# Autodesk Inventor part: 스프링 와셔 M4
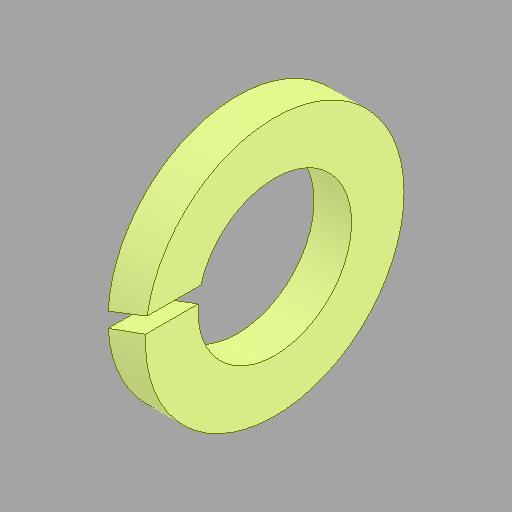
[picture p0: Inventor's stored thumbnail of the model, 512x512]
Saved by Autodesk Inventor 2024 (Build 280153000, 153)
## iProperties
Created: 2024-05
Part Number: 스프링 와셔 M4
Material: 강철, 연강
Description: 스프링 잠금 와셔
Document SubType Name: Modeling
Designer: kh_501
Density: 7.85 g/cm^3
Appearance: 기본값
Author: jhkim
Sending System: Autodesk Inventor 2025
Preprocessor: ST-DEVELOPER v20
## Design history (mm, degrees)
node "스프링 와셔 M41"
node "솔리드1"
body "Solid1"
